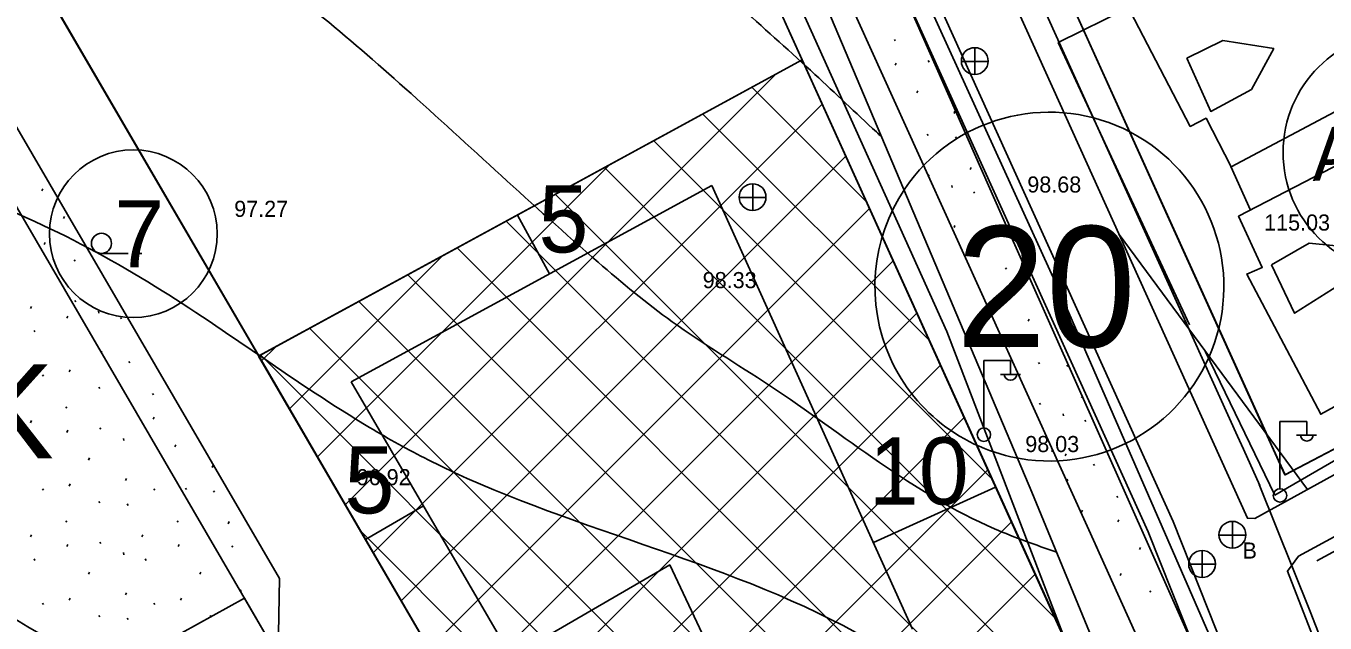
# Model space of a CAD drawing. Extents: x 412225 to 413380, y 4456471 to 4457189.
# Drawn here: x 412929 to 413025.8, y 4456625.2 to 4456669.7 of the extents above; entities that cross this region are included whole.
import ezdxf

# ---------------------------------------------------------------- set-up
doc = ezdxf.new("R2010")
doc.units = 0
for name, color, linetype in [('0_HALİHAZIR', 7, 'Continuous'), ('0_KADASTRO', 7, 'Continuous'), ('Level 20', 7, 'Continuous'), ('Level 27', 7, 'Continuous'), ('Level 28', 7, 'Continuous'), ('Level 31', 7, 'Continuous'), ('Level 34', 7, 'Continuous'), ('Level 41', 7, 'Continuous'), ('Level 57', 7, 'Continuous'), ('Level 58', 7, 'Continuous'), ('Level 62', 7, 'Continuous')]:
    doc.layers.add(name, color=color, linetype=linetype)

msp = doc.modelspace()

# ---------------------------------------------------------------- linework, layer by layer
at = {"layer": '0_HALİHAZIR'}
for p, q in [((412999.676, 4456666.112), (412999.676, 4456668.112)), ((412998.656, 4456667.102), (413000.656, 4456667.102)), ((412983.118, 4456655.974), (412983.118, 4456657.974)), ((412982.098, 4456656.964), (412984.098, 4456656.964)), ((413024.453, 4456635.201), (413010.417, 4456654.198)), ((412934.589, 4456652.788), (412936.589, 4456652.788)), ((412936.889, 4456652.788), (412937.089, 4456652.788)), ((412937.389, 4456652.788), (412937.589, 4456652.788)), ((413000.329, 4456639.807), (413000.329, 4456644.807)), ((413000.329, 4456644.807), (413002.329, 4456644.807)), ((413002.329, 4456643.807), (413002.329, 4456644.807)), ((413001.569, 4456643.767), (413003.069, 4456643.767)), ((413022.392, 4456635.274), (413022.392, 4456640.274)), ((413022.392, 4456640.274), (413024.392, 4456640.274)), ((413024.392, 4456639.274), (413024.392, 4456640.274)), ((413023.632, 4456639.234), (413025.132, 4456639.234)), ((413018.871, 4456630.811), (413018.871, 4456632.811)), ((413017.851, 4456631.801), (413019.851, 4456631.801)), ((413016.615, 4456628.633), (413016.615, 4456630.634)), ((413015.595, 4456629.624), (413017.595, 4456629.624))]:
    msp.add_line(p, q, dxfattribs=at)
for points in [[(412943.324, 4456790.057), (412939.491, 4456799.046), (412938.705, 4456800.919), (412938.051, 4456803.147), (412937.963, 4456804.315), (412938.189, 4456805.139), (412938.852, 4456805.5), (412939.848, 4456804.725), (412960.321, 4456752.926), (412986.83, 4456691.988), (413005.898, 4456650.126), (413022.776, 4456611.403), (413022.909, 4456610.593), (413022.798, 4456610.051), (413022.687, 4456609.84), (413022.549, 4456609.659), (413022.068, 4456609.794), (413001.616, 4456655.726), (412969.952, 4456727.404), (412949.891, 4456775.519)], [(413018.765, 4456659.249), (413016.895, 4456662.86), (413015.715, 4456662.255), (413010.285, 4456672.677), (413010.317, 4456672.716), (413029.75, 4456682.615), (413034.842, 4456672.467), (413033.583, 4456671.685), (413035.382, 4456668.057)], [(413015.462, 4456667.329), (413017.239, 4456663.366), (413020.271, 4456665.007), (413021.94, 4456668.06), (413018.155, 4456668.657)], [(413053.405, 4456615.195), (413033.074, 4456604.112), (413032.56, 4456604.434), (413022.955, 4456629.103), (413023.782, 4456630.234), (413078.443, 4456659.87), (413091.421, 4456666.304), (413091.726, 4456666.393), (413092.222, 4456666.272), (413100.074, 4456649.285), (413101.857, 4456643.728), (413101.722, 4456643.302), (413071.701, 4456625.367)], [(413036.143, 4456664.28), (413037.946, 4456660.723), (413038.935, 4456661.526), (413044.411, 4456651.232), (413025.434, 4456640.803), (413019.925, 4456651.249), (413021.08, 4456651.744), (413019.32, 4456655.561)], [(413021.77, 4456651.928), (413023.486, 4456648.334), (413026.788, 4456650.433), (413028.351, 4456653.19), (413024.568, 4456653.565)], [(412961.452, 4456615.771), (412959.402, 4456619.385), (412976.935, 4456629.577), (412979.559, 4456624.048), (412968.019, 4456617.756), (412975.759, 4456603.45), (412974.281, 4456602.538), (412980.344, 4456591.82), (412976.793, 4456589.684)]]:
    msp.add_lwpolyline(points, close=True, dxfattribs=at)
for points in [[(412813.007, 4456650.071), (412835.489, 4456664.933), (412867.464, 4456683.962), (412901.181, 4456703.969), (412934.85, 4456721.065), (412956.754, 4456731.07), (412958.117, 4456731.459), (412959.035, 4456731.634), (412960.277, 4456731.39), (412961.32, 4456730.801), (412962.336, 4456729.858), (412972.363, 4456705.953), (412988.995, 4456670.284), (413003.917, 4456634.999), (413014.424, 4456609.495), (413014.707, 4456606.962), (413014.677, 4456605.697), (413014.483, 4456604.379), (413013.724, 4456603.316), (412984.218, 4456588.075)], [(412964.983, 4456716.036), (412975.141, 4456695.7), (412987.131, 4456670.137), (412997.579, 4456646.975), (413006.23, 4456624.443), (413011.441, 4456610.697), (413011.993, 4456607.031), (413011.051, 4456604.64), (413008.65, 4456602.35), (413006.829, 4456601.453), (413005.857, 4456601.375)], [(413089.49, 4456670.569), (413086.329, 4456669.044), (413084.893, 4456668.397), (413076.51, 4456664.142), (413046.894, 4456647.575), (413020.531, 4456633.039), (413019.975, 4456633.047), (413001.403, 4456674.145)], [(413015.647, 4456647.478), (413005.879, 4456668.5), (413011.111, 4456671.093)], [(413018.751, 4456659.276), (413020.211, 4456656.023), (413020.208, 4456656.028)], [(413025.138, 4456629.878), (413051.074, 4456643.946), (413071.616, 4456654.407), (413072.633, 4456650.989)], [(413054.005, 4456653.307), (413022.025, 4456634.777), (413016.822, 4456645.51)]]:
    msp.add_lwpolyline(points, dxfattribs=at)
for centre, radius in [((412999.661, 4456667.12), 1), ((412983.103, 4456656.982), 1), ((412934.589, 4456653.538), 0.75), ((413000.339, 4456639.283), 0.5), ((413022.402, 4456634.75), 0.5), ((413018.856, 4456631.819), 1), ((413016.6, 4456629.642), 1)]:
    msp.add_circle(centre, radius, dxfattribs=at)
for centre in [(413002.329, 4456643.811), (413024.392, 4456639.278)]:
    msp.add_arc(centre, 0.474, 184.83843, 355.14641, dxfattribs=at)
for points in [[(412992.716, 4456661.485), (412992.328, 4456661.842), (412987.746, 4456666.132), (412977.092, 4456675.902), (412971.542, 4456680.769), (412970.43, 4456681.421), (412953.379, 4456688.33), (412947.814, 4456691.709), (412935.217, 4456702.348), (412927.264, 4456711.821), (412925.031, 4456716.079)], [(413005.761, 4456630.522), (413001.136, 4456632.263), (412984.376, 4456642.94), (412977.117, 4456647.694), (412971.593, 4456652.141), (412957.205, 4456665.099), (412943.851, 4456675.858), (412940.258, 4456678.239), (412939.048, 4456679.041), (412936.231, 4456681.076), (412913.981, 4456697.425), (412905.411, 4456706.117)], [(413011.724, 4456606.102), (412995.239, 4456621.045), (412991.947, 4456623.876), (412990.801, 4456624.547), (412958.936, 4456637.403), (412954.567, 4456639.817), (412938.594, 4456650.328), (412929.62, 4456655.175), (412907.019, 4456665.994), (412895.993, 4456677.467), (412894.135, 4456680.08), (412893.583, 4456681.1), (412886.792, 4456695.431)], [(412954.779, 4456612.553), (412952.206, 4456613.697), (412941.009, 4456618.727), (412920.288, 4456630.573), (412911.175, 4456637.709), (412908.09, 4456640.597), (412896.792, 4456650.717), (412890.704, 4456656.374), (412889.418, 4456657.685), (412876.396, 4456672.773), (412875.794, 4456673.634), (412875.1, 4456674.94), (412874.235, 4456677.292), (412871.061, 4456682.644), (412869.151, 4456684.963)]]:
    msp.add_spline(points, degree=3, dxfattribs=at)
at = {"layer": '0_KADASTRO'}
for points in [[(412920.19, 4456689.98), (412964.24, 4456717.02), (412964.813, 4456715.755), (412986.81, 4456667.21), (412946.31, 4456645.15), (412920.457, 4456689.522)], [(413005.79, 4456673.79), (413056.06, 4456699.54), (413063.81, 4456681.11), (413045.52, 4456671.73), (413053.62, 4456652.47), (413039.5, 4456645.06), (413022.77, 4456636.28), (413014.03, 4456655.6)], [(412877.7, 4456663.9), (412892.499, 4456672.986), (412911.66, 4456684.75), (412947.76, 4456622.78), (412914.4, 4456604.32)], [(412935.96, 4456608.27), (412960.03, 4456621.59), (412946.31, 4456645.15), (412986.81, 4456667.21), (413002.41, 4456632.76), (413015.38, 4456604.15), (412956.24, 4456576.51), (412943.63, 4456596.26), (412939.32, 4456603.01)]]:
    msp.add_lwpolyline(points, close=True, dxfattribs=at)
at = {"layer": 'Level 20'}
for p, q in [((412953.207, 4456643.213), (412980.057, 4456657.838)), ((412980.057, 4456657.838), (412995.03, 4456624.795)), ((412965.584, 4456655.648), (412967.976, 4456651.257)), ((412966.908, 4456619.687), (412953.207, 4456643.213)), ((413001.216, 4456635.371), (412992.108, 4456631.243)), ((412954.257, 4456631.474), (412958.578, 4456633.99))]:
    msp.add_line(p, q, dxfattribs=at)
at = {"layer": 'Level 27'}
for points in [[(413021.484, 4456639.146), (413005.79, 4456673.79)], [(413071.84, 4456662.04), (413053.62, 4456652.47), (413039.5, 4456645.06), (413022.779, 4456636.285)], [(413022.779, 4456636.285), (413021.483, 4456639.145)]]:
    msp.add_lwpolyline(points, dxfattribs=at)
at = {"layer": 'Level 28'}
for p, q in [((412946.262, 4456645.202), (412920.449, 4456689.517)), ((412914.219, 4456686.306), (412947.85, 4456628.567)), ((412985.552, 4456669.941), (413004.14, 4456628.919)), ((412960.016, 4456621.586), (412946.297, 4456645.143)), ((412947.85, 4456628.567), (412947.76, 4456622.803)), ((413004.14, 4456628.919), (413015.35, 4456604.131))]:
    msp.add_line(p, q, dxfattribs=at)
at = {"layer": 'Level 31'}
msp.add_circle((413031.633, 4456660.314), 9, dxfattribs=at)
at = {"layer": 'Level 34'}
for p, q in [((412986.722, 4456667.162), (412986.885, 4456667)), ((412952.757, 4456634.05), (412984.848, 4456666.141)), ((412983.06, 4456665.167), (412991.572, 4456656.656)), ((412954.839, 4456630.475), (412988.281, 4456663.918)), ((412979.398, 4456663.173), (412996.259, 4456646.312)), ((412975.736, 4456661.178), (413000.946, 4456635.968)), ((412956.921, 4456626.9), (412990.045, 4456660.025)), ((412950.675, 4456637.625), (412972.424, 4456659.374)), ((412972.074, 4456659.183), (413005.628, 4456625.629)), ((412968.412, 4456657.189), (413010.298, 4456615.302)), ((412959.003, 4456623.325), (412991.809, 4456656.132)), ((412964.75, 4456655.194), (413014.968, 4456604.975)), ((412961.087, 4456653.199), (413011.81, 4456602.477)), ((412941.269, 4456599.935), (412993.573, 4456652.239)), ((412948.593, 4456641.2), (412960, 4456652.607)), ((412957.425, 4456651.204), (413007.955, 4456600.675)), ((412953.763, 4456649.21), (413004.099, 4456598.874)), ((412943.474, 4456596.483), (412995.337, 4456648.346)), ((412950.101, 4456647.215), (413000.244, 4456597.072)), ((412946.439, 4456645.22), (412996.389, 4456595.27)), ((412946.511, 4456644.775), (412947.576, 4456645.839)), ((412945.679, 4456593.031), (412997.101, 4456644.453)), ((412947.883, 4456589.578), (412998.865, 4456640.56)), ((412950.088, 4456586.126), (413000.629, 4456636.667)), ((412952.292, 4456582.674), (413002.393, 4456632.774)), ((412953.879, 4456632.123), (412992.533, 4456593.469)), ((412954.497, 4456579.222), (413004.157, 4456628.882))]:
    msp.add_line(p, q, dxfattribs=at)
at = {"layer": 'Level 41'}
for p, q in [((412993.668, 4456668.737), (412993.739, 4456668.63)), ((412996.191, 4456667.16), (412996.262, 4456667.053)), ((412993.726, 4456666.815), (412993.798, 4456666.975)), ((412995.342, 4456664.755), (412995.414, 4456664.915)), ((412998.114, 4456663.225), (412998.184, 4456663.385)), ((412996.124, 4456661.68), (412996.195, 4456661.573)), ((412998.223, 4456661.488), (412998.294, 4456661.381)), ((412996.191, 4456658.65), (412996.262, 4456658.543)), ((412999.32, 4456659.034), (412999.391, 4456659.193)), ((412930.152, 4456657.447), (412930.224, 4456657.607)), ((412997.949, 4456657.859), (412997.967, 4456657.699)), ((412999.579, 4456657.389), (412999.649, 4456657.282)), ((412931.768, 4456655.387), (412931.84, 4456655.547)), ((412998.114, 4456654.715), (412998.184, 4456654.875)), ((412930.33, 4456653.449), (412930.401, 4456653.609)), ((413000.209, 4456654.099), (413000.28, 4456653.993)), ((413002.197, 4456654.307), (413002.268, 4456654.467)), ((412932.55, 4456652.312), (412932.621, 4456652.205)), ((413001.961, 4456651.717), (413002.032, 4456651.61)), ((413002.019, 4456649.795), (413002.091, 4456649.955)), ((412929.306, 4456648.685), (412929.377, 4456648.844)), ((412932.617, 4456649.282), (412932.688, 4456649.175)), ((412932.005, 4456647.956), (412932.077, 4456648.116)), ((412934.375, 4456648.491), (412934.393, 4456648.331)), ((412936.005, 4456648.021), (412936.075, 4456647.914)), ((413003.635, 4456647.735), (413003.707, 4456647.895)), ((412929.565, 4456647.04), (412929.635, 4456646.933)), ((413002.197, 4456645.797), (413002.268, 4456645.957)), ((412934.568, 4456645.411), (412934.61, 4456645.507)), ((412932.183, 4456643.958), (412932.254, 4456644.118)), ((412936.635, 4456644.731), (412936.706, 4456644.625)), ((413004.417, 4456644.66), (413004.488, 4456644.553)), ((413006.516, 4456644.468), (413006.587, 4456644.361)), ((412930.195, 4456643.75), (412930.266, 4456643.644)), ((412934.403, 4456642.821), (412934.474, 4456642.714)), ((412938.387, 4456642.349), (412938.458, 4456642.242)), ((413007.613, 4456642.014), (413007.684, 4456642.173)), ((412931.947, 4456641.368), (412932.018, 4456641.261)), ((413004.484, 4456641.63), (413004.555, 4456641.523)), ((412929.306, 4456640.175), (412929.377, 4456640.334)), ((412938.445, 4456640.427), (412938.517, 4456640.587)), ((413006.242, 4456640.839), (413006.26, 4456640.679)), ((413007.872, 4456640.369), (413007.942, 4456640.262)), ((412932.005, 4456639.446), (412932.077, 4456639.606)), ((412934.47, 4456639.791), (412934.541, 4456639.684)), ((412929.565, 4456638.53), (412929.635, 4456638.423)), ((412936.228, 4456639), (412936.246, 4456638.84)), ((412940.061, 4456638.367), (412940.133, 4456638.527)), ((412933.621, 4456637.386), (412933.693, 4456637.546)), ((413006.407, 4456637.695), (413006.477, 4456637.855)), ((412942.833, 4456636.837), (412942.903, 4456636.997)), ((413008.502, 4456637.079), (413008.573, 4456636.973)), ((412930.195, 4456635.24), (412930.266, 4456635.134)), ((412932.183, 4456635.448), (412932.254, 4456635.608)), ((412936.393, 4456635.856), (412936.463, 4456636.016)), ((412938.488, 4456635.24), (412938.559, 4456635.134)), ((412940.843, 4456635.292), (412940.914, 4456635.185)), ((413006.516, 4456635.958), (413006.587, 4456635.851)), ((412934.403, 4456634.311), (412934.474, 4456634.204)), ((412942.942, 4456635.1), (412943.013, 4456634.993)), ((413010.254, 4456634.697), (413010.325, 4456634.59)), ((412936.502, 4456634.119), (412936.573, 4456634.012)), ((413007.613, 4456633.504), (413007.684, 4456633.663)), ((412931.947, 4456632.858), (412932.018, 4456632.751)), ((412940.24, 4456632.858), (412940.311, 4456632.751)), ((412944.039, 4456632.646), (412944.11, 4456632.805)), ((413010.312, 4456632.775), (413010.384, 4456632.935)), ((412929.306, 4456631.665), (412929.377, 4456631.824)), ((412937.599, 4456631.665), (412937.67, 4456631.824)), ((412932.005, 4456630.936), (412932.077, 4456631.096)), ((412934.47, 4456631.281), (412934.541, 4456631.174)), ((412936.228, 4456630.49), (412936.246, 4456630.33)), ((412940.298, 4456630.936), (412940.37, 4456631.096)), ((412944.298, 4456631.001), (412944.368, 4456630.894)), ((413011.928, 4456630.715), (413012, 4456630.875)), ((412929.565, 4456630.02), (412929.635, 4456629.913)), ((412937.858, 4456630.02), (412937.928, 4456629.913)), ((412933.621, 4456628.876), (412933.693, 4456629.036)), ((412941.914, 4456628.876), (412941.986, 4456629.036)), ((413010.49, 4456628.777), (413010.561, 4456628.937)), ((412936.393, 4456627.346), (412936.463, 4456627.506)), ((412944.928, 4456627.711), (412944.999, 4456627.605)), ((413012.71, 4456627.64), (413012.781, 4456627.533)), ((412930.195, 4456626.73), (412930.266, 4456626.624)), ((412932.183, 4456626.938), (412932.254, 4456627.098)), ((412938.488, 4456626.73), (412938.559, 4456626.624)), ((412940.476, 4456626.938), (412940.547, 4456627.098)), ((412934.403, 4456625.801), (412934.474, 4456625.694)), ((412936.502, 4456625.609), (412936.573, 4456625.502)), ((412942.696, 4456625.801), (412942.767, 4456625.694))]:
    msp.add_line(p, q, dxfattribs=at)
at = {"layer": 'Level 57'}
msp.add_line((412946.297, 4456645.143), (412986.81, 4456667.21), dxfattribs=at)
msp.add_lwpolyline([(412947.767, 4456622.777), (412945.249, 4456627.098), (412934.75, 4456621.287), (412937.172, 4456616.912)], dxfattribs=at)
at = {"layer": 'Level 58'}
msp.add_circle((412936.964, 4456654.254), 6.25, dxfattribs=at)
for start, end in [(262.86125, 145.88957), (145.88957, 262.86125)]:
    msp.add_arc((413005.218, 4456650.317), 13, start, end, dxfattribs=at)
at = {"layer": 'Level 62'}
for p, q in [((413014.432, 4456632.805), (412976.104, 4456717.479)), ((413012.589, 4456632.028), (412974.395, 4456716.404)), ((412970.967, 4456714.246), (413008.746, 4456630.871)), ((413019.233, 4456639.174), (413001.608, 4456678.112)), ((413019.677, 4456638.193), (413019.233, 4456639.174)), ((413020.898, 4456635.495), (413019.677, 4456638.193)), ((413024.64, 4456626.092), (413020.862, 4456635.579)), ((413026.149, 4456603.386), (413014.432, 4456632.805)), ((413021.711, 4456609.126), (413012.589, 4456632.028)), ((413008.746, 4456630.871), (413008.696, 4456630.98)), ((413008.696, 4456630.98), (413019.142, 4456607.882)), ((413036.409, 4456596.544), (413024.64, 4456626.092))]:
    msp.add_line(p, q, dxfattribs=at)

# ---------------------------------------------------------------- texts
at = {"layer": '0_HALİHAZIR'}
for s, p in [('98.68', (413003.575, 4456657.326)), ('97.27', (412944.483, 4456655.512)), ('115.03', (413021.222, 4456654.491)), ('98.33', (412979.389, 4456650.2)), ('98.03', (413003.424, 4456637.983)), ('96.92', (412953.609, 4456635.514)), ('B', (413019.612, 4456630.048))]:
    msp.add_text(s, height=1.2, dxfattribs=at).set_placement(p)
at = {"layer": 'Level 20'}
for s, p in [('5', (412967.152, 4456652.861)), ('10', (412991.775, 4456634.077)), ('5', (412952.698, 4456633.415))]:
    msp.add_text(s, height=5, dxfattribs=at).set_placement(p)
at = {"layer": 'Level 31'}
msp.add_text('A  ', height=4, rotation=1, dxfattribs=at).set_placement((413024.836, 4456658.195))
at = {"layer": 'Level 41'}
msp.add_text('PARK', height=7, dxfattribs=at).set_placement((412905.555, 4456637.517))
at = {"layer": 'Level 58'}
for s, height, p in [('7', 5, (412935.546, 4456651.755)), ('20', 9, (412998.274, 4456645.817))]:
    msp.add_text(s, height=height, dxfattribs=at).set_placement(p)

doc.saveas('drawing.dxf')
